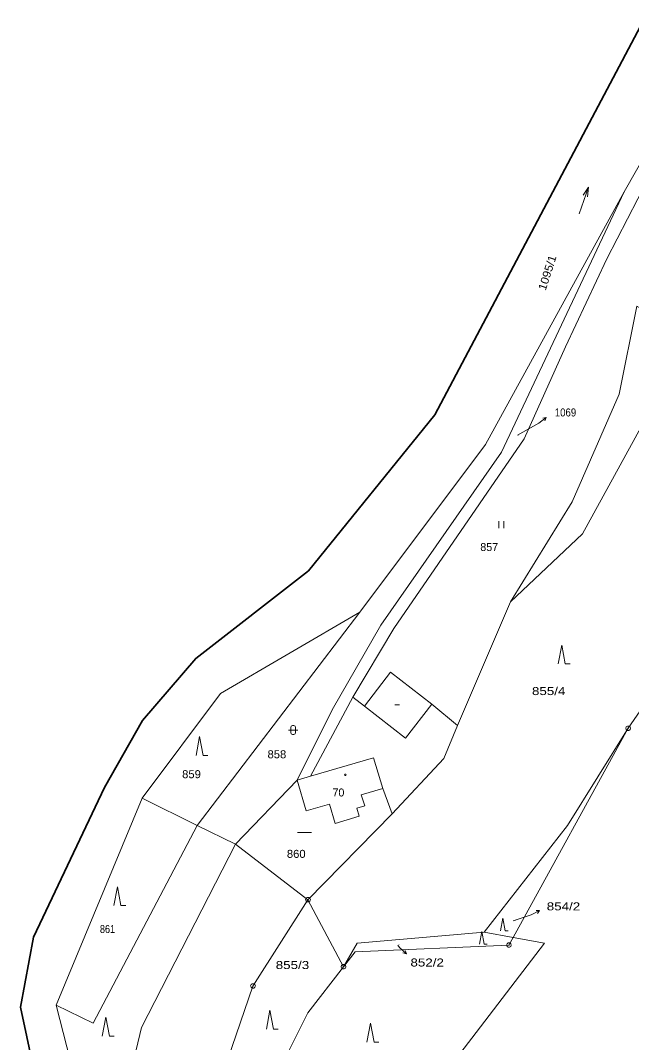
# Model space of a CAD drawing. Extents: x -687390 to -684106, y -954833 to -951648.
# Drawn here: x -687321 to -687191.2, y -953586.1 to -953369.1 of the extents above; entities that cross this region are included whole.
import ezdxf

# ---------------------------------------------------------------- set-up
doc = ezdxf.new("R2010")
doc.units = 0
doc.header["$LTSCALE"] = 0.68
for name, color, linetype, lineweight in [('1', 7, 'Continuous', 13), ('3', 7, 'Continuous', 13), ('4', 7, 'Continuous', 13), ('5', 7, 'Continuous', 13), ('7', 7, 'Continuous', 13), ('8', 7, 'Continuous', 13)]:
    doc.layers.add(name, color=color, linetype=linetype, lineweight=lineweight)
doc.layers.add('2', color=7, linetype='Continuous')

msp = doc.modelspace()

# ---------------------------------------------------------------- linework, layer by layer
at = {"layer": '1', "lineweight": 35}
for p, q in [((-687232.93, -953452.82), (-687188.65, -953369.08)), ((-687232.93, -953452.82), (-687259.81, -953485.94)), ((-687318.21, -953563.75), (-687320.97, -953578.62)), ((-687320.97, -953578.62), (-687307.81, -953640.21))]:
    msp.add_line(p, q, dxfattribs=at)
at = {"layer": '1'}
for p, q in [((-687187.64, -953402.72), (-687196.41, -953419.69)), ((-687205.22, -953438.38), (-687196.41, -953419.69)), ((-687213.96, -953457.96), (-687205.22, -953438.38)), ((-687213.96, -953457.96), (-687241.68, -953498.22)), ((-687250.37, -953512.78), (-687241.68, -953498.22)), ((-687262.19, -953530.42), (-687254.77, -953515.5)), ((-687216.31, -953563.81), (-687191.88, -953519.4)), ((-687191.88, -953519.4), (-687204.75, -953540.04)), ((-687259.37, -953529.59), (-687262.19, -953530.42)), ((-687295.14, -953534.26), (-687313.41, -953578.17)), ((-687222.45, -953562.71), (-687204.75, -953540.04)), ((-687216.31, -953563.81), (-687222.45, -953562.71)), ((-687217.2, -953565.43), (-687216.31, -953563.81)), ((-687209.64, -953564.99), (-687216.31, -953563.81)), ((-687295.24, -953582.94), (-687303.52, -953616.63))]:
    msp.add_line(p, q, dxfattribs=at)
for points in [[(-687178.53, -953380.51), (-687192.76, -953405.49), (-687218.75, -953460.74), (-687244.43, -953497.5), (-687254.77, -953515.5)], [(-687192.76, -953405.49), (-687222.2, -953459.13), (-687248.89, -953494.77), (-687278.49, -953512.02), (-687295.14, -953534.26)], [(-687228.11, -953518.77), (-687216.87, -953492.55), (-687201.57, -953478.07), (-687187.98, -953453.34), (-687176.19, -953437.73), (-687190.07, -953429.77), (-687193.81, -953448.45), (-687203.76, -953471.34), (-687216.87, -953492.55)], [(-687154.74, -953462.77), (-687147.69, -953470.76), (-687173.1, -953492.29), (-687191.88, -953519.4)], [(-687303.52, -953616.63), (-687313.41, -953578.17), (-687305.51, -953582.02), (-687283.42, -953540.01), (-687248.89, -953494.77)], [(-687247.89, -953514.67), (-687242.34, -953507.45), (-687233.59, -953514.29)], [(-687247.89, -953514.67), (-687250.37, -953512.78), (-687259.37, -953529.59)], [(-687242.02, -953537.53), (-687231.02, -953525.84), (-687228.11, -953518.77), (-687233.59, -953514.29)], [(-687275.28, -953544.01), (-687262.19, -953530.42), (-687260.26, -953536.93), (-687255.35, -953535.51), (-687254.1, -953539.62), (-687249.02, -953538.09), (-687249.54, -953536.35), (-687247.83, -953535.84), (-687248.56, -953533.56), (-687243.97, -953532.16)], [(-687295.14, -953534.26), (-687283.42, -953540.01), (-687275.28, -953544.01)], [(-687259.89, -953555.79), (-687242.02, -953537.53), (-687243.97, -953532.16)], [(-687295.24, -953582.94), (-687275.28, -953544.01), (-687259.89, -953555.79)], [(-687259.89, -953555.79), (-687271.57, -953574.12), (-687282.2, -953605.18), (-687285.23, -953613.98), (-687282.93, -953645.9), (-687299.75, -953633.15)], [(-687259.89, -953555.79), (-687252.35, -953570.03), (-687259.92, -953579.82)], [(-687252.35, -953570.03), (-687249.42, -953565), (-687222.45, -953562.71)], [(-687209.64, -953564.99), (-687241.21, -953606.29), (-687272.84, -953605.61)], [(-687217.2, -953565.43), (-687249.89, -953566.84), (-687252.35, -953570.03)], [(-687259.92, -953579.82), (-687272.84, -953605.61), (-687282.2, -953605.18)]]:
    msp.add_lwpolyline(points, dxfattribs=at)
at = {"layer": '1', "lineweight": 35}
msp.add_lwpolyline([(-687318.21, -953563.75), (-687303.14, -953531.98), (-687295.06, -953517.76), (-687283.73, -953504.55), (-687259.81, -953485.94)], dxfattribs=at)
at = {"layer": '3'}
for p, q in [((-687202.301, -953410.141), (-687200.319, -953404.479)), ((-687219.32, -953475.43), (-687219.32, -953476.93)), ((-687218.32, -953476.93), (-687218.32, -953475.43)), ((-687262.13, -953541.53), (-687259.13, -953541.53))]:
    msp.add_line(p, q, dxfattribs=at)
for points in [[(-687201.451, -953406.201), (-687200.319, -953404.479), (-687200.508, -953406.531)], [(-687206.73, -953505.72), (-687205.98, -953501.72), (-687205.23, -953505.72), (-687204.23, -953505.72)], [(-687283.66, -953525.16), (-687282.91, -953521.16), (-687282.16, -953525.16), (-687281.16, -953525.16)], [(-687264.03, -953519.76), (-687262.76, -953519.76), (-687262.03, -953519.76)], [(-687301.11, -953557.03), (-687300.36, -953553.03), (-687299.61, -953557.03), (-687298.61, -953557.03)], [(-687219.022, -953562.42), (-687218.52, -953559.74), (-687218.018, -953562.42), (-687217.348, -953562.42)], [(-687223.472, -953565.25), (-687222.97, -953562.57), (-687222.468, -953565.25), (-687221.798, -953565.25)], [(-687268.73, -953583.28), (-687267.98, -953579.28), (-687267.23, -953583.28), (-687266.23, -953583.28)], [(-687303.58, -953584.75), (-687302.83, -953580.75), (-687302.08, -953584.75), (-687301.08, -953584.75)], [(-687247.36, -953586.04), (-687246.61, -953582.04), (-687245.86, -953586.04), (-687244.86, -953586.04)]]:
    msp.add_lwpolyline(points, dxfattribs=at)
msp.add_lwpolyline([(-687263.53, -953519.26), (-687263.43, -953518.97), (-687263.18, -953518.79), (-687262.87, -953518.79), (-687262.62, -953518.97), (-687262.52, -953519.26), (-687262.52, -953520.26), (-687262.62, -953520.55), (-687262.87, -953520.73), (-687263.18, -953520.73), (-687263.43, -953520.55), (-687263.53, -953520.26)], close=True, dxfattribs=at)
at = {"layer": '4'}
for points in [[(-687233.59, -953514.29), (-687239.16, -953521.52), (-687247.89, -953514.67)], [(-687243.97, -953532.16), (-687245.95, -953525.65), (-687259.37, -953529.59)]]:
    msp.add_lwpolyline(points, dxfattribs=at)
at = {"layer": '5'}
msp.add_line((-687241.43, -953514.42), (-687240.43, -953514.42), dxfattribs=at)
msp.add_lwpolyline([(-687251.88, -953529.13), (-687251.79, -953529.28), (-687251.88, -953529.43), (-687252.06, -953529.43), (-687252.15, -953529.28), (-687252.06, -953529.13)], close=True, dxfattribs=at)
at = {"layer": '7'}
for p, q in [((-687209.268, -953453.416), (-687210.87, -953454.63)), ((-687215.41, -953457.15), (-687210.87, -953454.63)), ((-687210.703, -953558.119), (-687212.5, -953559.02)), ((-687216.29, -953560.29), (-687212.5, -953559.02)), ((-687240.78, -953565.47), (-687240.44, -953565.92)), ((-687238.993, -953567.315), (-687240.44, -953565.92))]:
    msp.add_line(p, q, dxfattribs=at)
for points in [[(-687210.004, -953453.554), (-687209.268, -953453.416), (-687209.6, -953454.088)], [(-687211.452, -953558.12), (-687210.703, -953558.119), (-687211.152, -953558.719)], [(-687239.243, -953566.609), (-687238.993, -953567.315), (-687239.708, -953567.091)]]:
    msp.add_lwpolyline(points, dxfattribs=at)
at = {"layer": '8'}
for p, q in [((-687192, -953519.4), (-687191.76, -953519.4)), ((-687260.01, -953555.79), (-687259.77, -953555.79)), ((-687217.32, -953565.43), (-687217.08, -953565.43)), ((-687252.47, -953570.03), (-687252.23, -953570.03)), ((-687271.69, -953574.12), (-687271.45, -953574.12))]:
    msp.add_line(p, q, dxfattribs=at)
for points in [[(-687191.73, -953518.92), (-687191.48, -953519.1), (-687191.38, -953519.39), (-687191.48, -953519.68), (-687191.73, -953519.86), (-687192.04, -953519.86), (-687192.29, -953519.68), (-687192.39, -953519.39), (-687192.29, -953519.1), (-687192.04, -953518.92)], [(-687259.74, -953555.31), (-687259.49, -953555.49), (-687259.39, -953555.78), (-687259.49, -953556.07), (-687259.74, -953556.25), (-687260.05, -953556.25), (-687260.3, -953556.07), (-687260.4, -953555.78), (-687260.3, -953555.49), (-687260.05, -953555.31)], [(-687217.05, -953564.95), (-687216.8, -953565.13), (-687216.7, -953565.42), (-687216.8, -953565.71), (-687217.05, -953565.89), (-687217.36, -953565.89), (-687217.61, -953565.71), (-687217.71, -953565.42), (-687217.61, -953565.13), (-687217.36, -953564.95)], [(-687252.2, -953569.55), (-687251.95, -953569.73), (-687251.85, -953570.02), (-687251.95, -953570.31), (-687252.2, -953570.49), (-687252.51, -953570.49), (-687252.76, -953570.31), (-687252.86, -953570.02), (-687252.76, -953569.73), (-687252.51, -953569.55)], [(-687271.42, -953573.64), (-687271.17, -953573.82), (-687271.07, -953574.11), (-687271.17, -953574.4), (-687271.42, -953574.58), (-687271.73, -953574.58), (-687271.98, -953574.4), (-687272.08, -953574.11), (-687271.98, -953573.82), (-687271.73, -953573.64)]]:
    msp.add_lwpolyline(points, close=True, dxfattribs=at)

# ---------------------------------------------------------------- texts
at = {"layer": '2', "width": 1.1}
msp.add_text('1095/1', height=1.7, rotation=72.193, dxfattribs=at).set_placement((-687209.41, -953426.552))
at = {"layer": '2'}
for s, height, width, p in [('1069', 0.1, 0.9, (-687215.364, -953457.15)), ('855/4', 1.7, 1.25, (-687212.315, -953512.34)), ('858', 1.7, 1.05, (-687268.485, -953525.76)), ('859', 1.7, 1.05, (-687286.625, -953529.99)), ('860', 1.7, 1.05, (-687264.375, -953546.91)), ('854/2', 0.1, 1.25, (-687216.262, -953560.29)), ('861', 1.7, 0.85, (-687304.085, -953562.87)), ('852/2', 0.1, 1.25, (-687240.752, -953565.47)), ('855/3', 1.7, 1.25, (-687266.745, -953570.52))]:
    msp.add_text(s, height=height, dxfattribs=dict(at, width=width)).set_placement(p)
for s, p in [('857', (-687223.285, -953481.75)), ('70', (-687254.685, -953533.87))]:
    msp.add_text(s, height=1.7, dxfattribs=at).set_placement(p)
at = {"layer": '7'}
for s, width, p in [('1069', 0.9, (-687207.465, -953453.17)), ('854/2', 1.25, (-687209.175, -953558.06)), ('852/2', 1.25, (-687238.125, -953569.98))]:
    msp.add_text(s, height=1.7, dxfattribs=dict(at, width=width)).set_placement(p)

doc.saveas('drawing.dxf')
